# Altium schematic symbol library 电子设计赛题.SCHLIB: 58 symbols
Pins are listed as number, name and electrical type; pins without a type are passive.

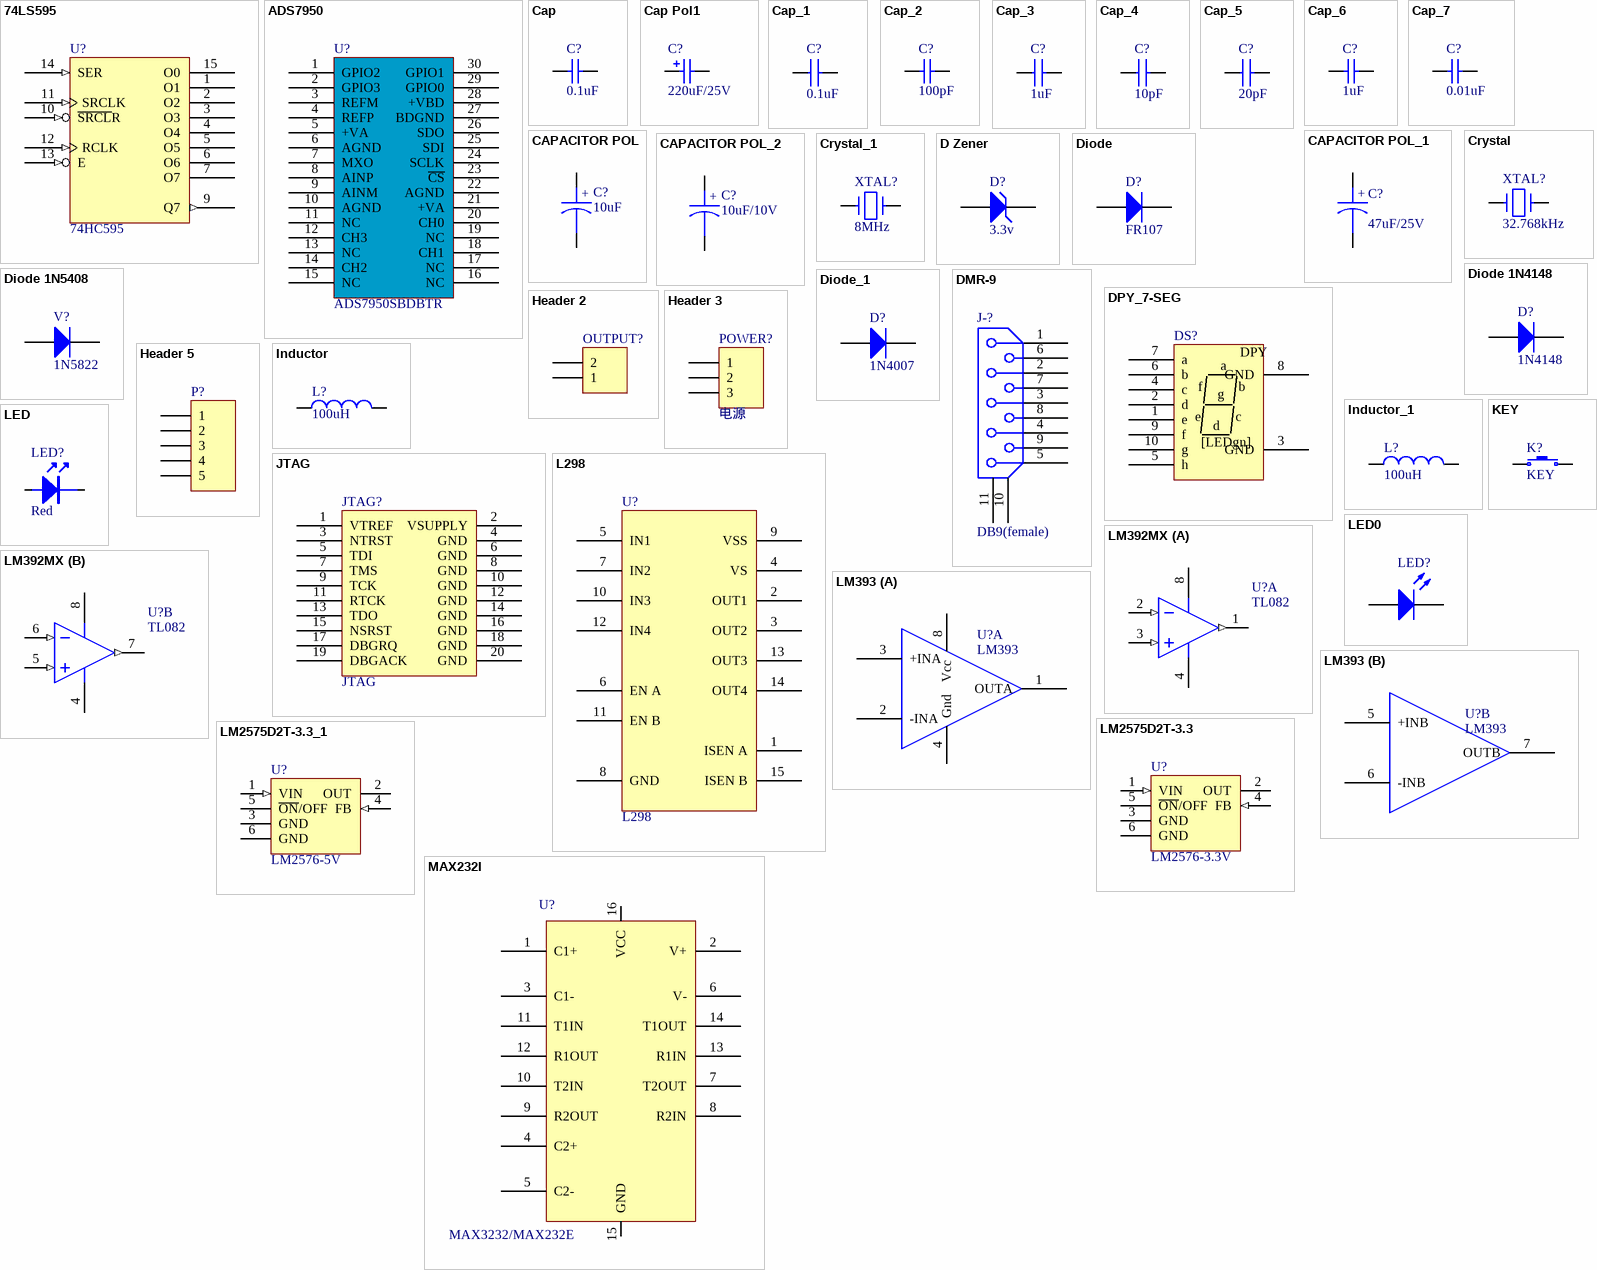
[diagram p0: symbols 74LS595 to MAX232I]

## 74LS595
designator U?, comment 74HC595
pins: 1 O1 (hiz), 2 O2 (hiz), 3 O3 (hiz), 4 O4 (hiz), 5 O5 (hiz), 6 O6 (hiz), 7 O7 (hiz), 8 GND (power) hidden to GND, 9 Q7 (out), 10 ~{SRCL}R (in), 11 SRCLK (in), 12 RCLK (in), 13 E (in), 14 SER (in), 15 O0 (hiz), 16 VCC (power) hidden to VCC

## ADS7950
designator U?, comment ADS7950SBDBTR
footprint LC-TSSOP-30
pins: 1 GPIO2, 2 GPIO3, 3 REFM, 4 REFP, 5 +VA, 6 AGND, 7 MXO, 8 AINP, 9 AINM, 10 AGND, 11 NC, 12 CH3, 13 NC, 14 CH2, 15 NC, 16 NC, 17 NC, 18 CH1, 19 NC, 20 CH0, 21 +VA, 22 AGND, 23 ~{CS}, 24 SCLK, 25 SDI, 26 SDO, 27 BDGND, 28 +VBD, 29 GPIO0, 30 GPIO1

## Cap
designator C?, comment 0.1uF
Capacitor
simulation model CAP (Capacitor)
signal-integrity model Cap
footprint LC-0805_C
pins: 1, 2

## Cap Pol1
designator C?, comment 220uF/25V
Polarized Capacitor (Radial)
simulation model CAP (Capacitor)
signal-integrity model Cap Pol
footprint CD-220uF-25V
pins: 1, 2
1 alternate drawing of the same symbol

## Cap_1
designator C?, comment 0.1uF
footprint LC-0805_C
pins: 1, 2

## Cap_2
designator C?, comment 100pF
Capacitor
simulation model CAP (Capacitor)
signal-integrity model Cap
footprint LC-0805_C
pins: 1, 2

## Cap_3
designator C?, comment 1uF
footprint LC-0805_C
pins: 1, 2

## Cap_4
designator C?, comment 10pF
footprint LC-0603_C
pins: 1, 2

## Cap_5
designator C?, comment 20pF
footprint LC-0603_C
pins: 1, 2

## Cap_6
designator C?, comment 1uF
Capacitor
simulation model CAP (Capacitor)
signal-integrity model Cap
footprint LC-0805_C
pins: 1, 2

## Cap_7
designator C?, comment 0.01uF
Capacitor
simulation model CAP (Capacitor)
signal-integrity model Cap
footprint LC-0603_C
pins: 1, 2

## CAPACITOR POL
designator C?, comment 10uF
Capacitor
footprint LC-0805_C
pins: 1, 2
2 alternate drawings of the same symbol

## CAPACITOR POL_1
designator C?, comment 47uF/25V
Capacitor
footprint LC-0603_C
pins: 1, 2
2 alternate drawings of the same symbol

## CAPACITOR POL_2
designator C?, comment 10uF/10V
Capacitor
footprint LC-0805_C
pins: 1, 2
2 alternate drawings of the same symbol

## Crystal
designator XTAL?, comment 32.768kHz
pins: 1, 2

## Crystal_1
designator XTAL?, comment 8MHz
pins: 1, 2

## D Zener
designator D?, comment 3.3v
Zener Diode
simulation model ZENER (Diode)
signal-integrity model D Zener
footprint LC-SOD-123
pins: 1 A, 2 K

## Diode
designator D?, comment FR107
Default Diode
simulation model DIODE (Diode)
signal-integrity model Diode
footprint 二极管  1N4007
pins: 1 A, 2 K

## Diode 1N4148
designator D?, comment 1N4148
High Conductance Fast Diode
footprint SMA
footprint LC-SMA(DO-214AC)_S4
pins: 1 A, 2 K

## Diode 1N5408
designator V?, comment 1N5822
3 Amp Medium Power Silicon Rectifier Diode
simulation model 1N5408 (DIODE)
signal-integrity model 1N5408
footprint SMA
footprint SMA
footprint LC-SMA(DO-214AC)_S4
pins: 1 A, 2 K

## Diode_1
designator D?, comment 1N4007
footprint LC-SMA(DO-214AC)_S1
pins: 1 A, 2 K

## DMR-9
designator J-?, comment DB9(female)
footprint DSUB1.385-2H9
pins: 1, 2, 3, 4, 5, 6, 7, 8, 9, 10, 11
2 alternate drawings of the same symbol

## DPY_7-SEG
designator DS?
Seven-Segment Display
footprint 数码管0.52 (LED, 7-Segment Display, 13 mm, RHD; 10 Leads; Row Space 15.24 mm; Pitch 2.54 mm)
pins: 1 e, 2 d, 3 GND, 4 c, 5 h, 6 b, 7 a, 8 GND, 9 f, 10 g

## Header 2
designator OUTPUT?, comment 2P端子  (value not drawn)
Header, 2-Pin
signal-integrity model Connector
footprint P485 (5mm间距485端子)
pins: 1, 2

## Header 3
designator POWER?, comment 电源
Header, 3-Pin
signal-integrity model Connector
footprint P485-3
pins: 1, 2, 3

## Header 5
designator P?  (value not drawn)
Header, 5-Pin
signal-integrity model Connector
footprint 2.54/5P
pins: 1, 2, 3, 4, 5

## Inductor
designator L?, comment 100uH
Inductor; Code_IEC: 1005
simulation model INDUCTOR (Inductor)
signal-integrity model Inductor
footprint CDRH125
pins: 1, 2

## Inductor_1
designator L?, comment 100uH
footprint LC-0805_R
pins: 1, 2

## JTAG
designator JTAG?
footprint IDC20 (2.54mm*20)
pins: 1 VTREF, 2 VSUPPLY, 3 NTRST, 4 GND, 5 TDI, 6 GND, 7 TMS, 8 GND, 9 TCK, 10 GND, 11 RTCK, 12 GND, 13 TDO, 14 GND, 15 NSRST, 16 GND, 17 DBGRQ, 18 GND, 19 DBGACK, 20 GND

## KEY
designator K?
footprint AN6X6
pins: 1, 2

## L298
designator U?
footprint L298
pins: 1 ISEN A, 2 OUT1, 3 OUT2, 4 VS, 5 IN1, 6 EN A, 7 IN2, 8 GND, 9 VSS, 10 IN3, 11 EN B, 12 IN4, 13 OUT3, 14 OUT4, 15 ISEN B

## LED
designator LED?, comment Red
footprint LC-0603_LED_S4
pins: 1, 2

## LED0
designator LED?, comment LED  (value not drawn)
Typical INFRARED GaAs LED
simulation model LED0 (Diode)
footprint LC-0805_LED_S1
pins: 1 A, 2 K

## LM392MX
designator U?, comment TL082
Low Power Operational Amplifier/Voltage Comparator; PartNumber: LM392MX; Manufacturer: National Semiconductor; PackageTopMarking: NSZXTT*LM392*M
footprint SOIC--8
footprint LC-SOIC-8_150mil
pins on every part: 4 GND (power), 8 V+ (power)
part A pins: 1 OUTA (out), 2 INA- (in), 3 INA+ (in)
part B pins: 5 INB+ (in), 6 INB- (in), 7 OUTB (out)

## LM393
designator U?
footprint SOIC--8
footprint LC-SOIC-8_150mil
part A pins: 1 OUTA, 2 -INA, 3 +INA, 4 Gnd, 8 Vcc
part B pins: 5 +INB, 6 -INB, 7 OUTB

## LM2575D2T-3.3
designator U?, comment LM2576-3.3V
Easy Switcher 1.0A Step-Down Voltage Regulator; Note: Pin 3 is electrically connected to Pin 6;Pin 6 is heatsink
footprint LC-TO-263-5
pins: 1 VIN (in), 2 OUT (oe), 3 GND (power), 4 FB (in), 5 ~{ON}/OFF, 6 GND (power)

## LM2575D2T-3.3_1
designator U?, comment LM2576-5V
Easy Switcher 1.0A Step-Down Voltage Regulator; Note: Pin 3 is electrically connected to Pin 6;Pin 6 is heatsink
footprint LC-TO-263-5
pins: 1 VIN (in), 2 OUT (oe), 3 GND (power), 4 FB (in), 5 ~{ON}/OFF, 6 GND (power)

## MAX232I
designator U?, comment MAX3232/MAX232E
Text Field1: 100; Text Field2: 200
footprint LC-SOIC-16_300mil
footprint LC-SOIC-16_300mil
footprint LC-SOP-16_300mil
pins: 1 C1+, 2 V+, 3 C1-, 4 C2+, 5 C2-, 6 V-, 7 T2OUT, 8 R2IN, 9 R2OUT, 10 T2IN, 11 T1IN, 12 R1OUT, 13 R1IN, 14 T1OUT, 15 GND, 16 VCC
2 alternate drawings of the same symbol

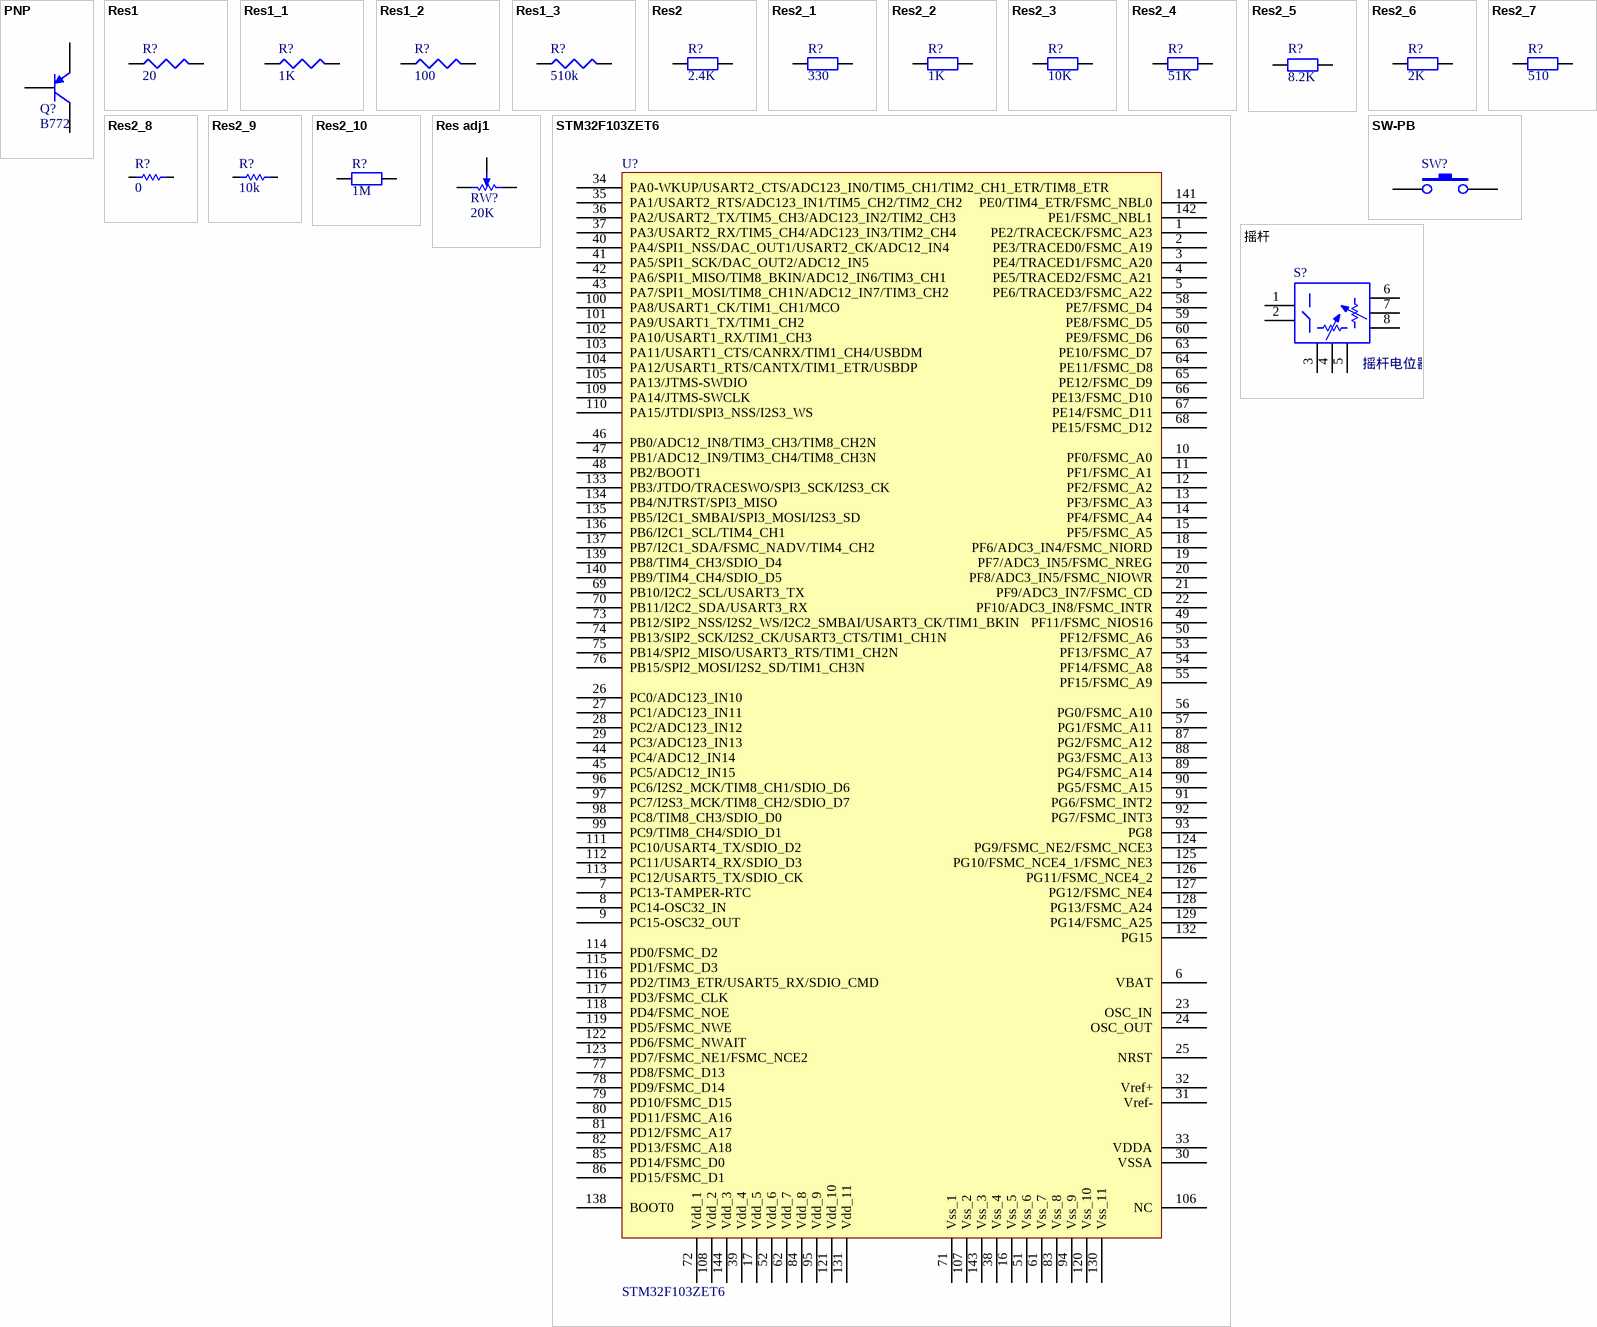
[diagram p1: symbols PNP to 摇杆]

## PNP
designator Q?, comment B772
PNP Bipolar Transistor
footprint SOT-23B_L (SOT23, 3-Leads, Body 2.9x1.3mm, Pitch 0.95mm, Lead Span 2.4mm, IPC High Density)
simulation model PNP
signal-integrity model PNP
pins: 1 B, 2 C, 3 E

## Res1
designator R?, comment 20
footprint LC-0805_R
pins: 1, 2

## Res1_1
designator R?, comment 1K
footprint LC-0805_R
pins: 1, 2

## Res1_2
designator R?, comment 100
footprint LC-0805_R
pins: 1, 2

## Res1_3
designator R?, comment 510k
footprint LC-0805_R
pins: 1, 2

## Res2
designator R?, comment 2.4K
Resistor
simulation model RESISTOR (Resistor)
signal-integrity model Res
footprint LC-0805_R
pins: 1, 2

## Res2_1
designator R?, comment 330
Resistor
simulation model RESISTOR (Resistor)
signal-integrity model Res
footprint LC-0805_R
pins: 1, 2

## Res2_2
designator R?, comment 1K
Resistor
simulation model RESISTOR (Resistor)
signal-integrity model Res
footprint LC-0805_R
pins: 1, 2

## Res2_3
designator R?, comment 10K
Resistor
simulation model RESISTOR (Resistor)
signal-integrity model Res
footprint LC-0805_R
pins: 1, 2

## Res2_4
designator R?, comment 51K
Resistor
simulation model RESISTOR (Resistor)
signal-integrity model Res
footprint LC-0805_R
pins: 1, 2

## Res2_5
designator R?, comment 8.2K
Resistor
simulation model RESISTOR (Resistor)
signal-integrity model Res
footprint LC-0805_R
pins: 1, 2

## Res2_6
designator R?, comment 2K
Resistor
simulation model RESISTOR (Resistor)
signal-integrity model Res
footprint LC-0805_R
pins: 1, 2

## Res2_7
designator R?, comment 510
Resistor
simulation model RESISTOR (Resistor)
signal-integrity model Res
footprint LC-0805_R
pins: 1, 2

## Res2_8
designator R?, comment 0
footprint LC-0805_R
pins: 1, 2

## Res2_9
designator R?, comment 10k
footprint LC-0805_R
pins: 1, 2

## Res2_10
designator R?, comment 1M
Resistor
simulation model RESISTOR (Resistor)
signal-integrity model Res
footprint LC-0603_R
pins: 1, 2

## Res adj1
designator RW?, comment 20K
footprint 3296W
pins: 1, 2, 3

## STM32F103ZET6
designator U?
footprint LC-TQFP-144_20x20x05P
footprint LC-LQFP-144_20x20x05P
pins: 1 PE2/TRACECK/FSMC_A23, 2 PE3/TRACED0/FSMC_A19, 3 PE4/TRACED1/FSMC_A20, 4 PE5/TRACED2/FSMC_A21, 5 PE6/TRACED3/FSMC_A22, 6 VBAT, 7 PC13-TAMPER-RTC, 8 PC14-OSC32_IN, 9 PC15-OSC32_OUT, 10 PF0/FSMC_A0, 11 PF1/FSMC_A1, 12 PF2/FSMC_A2, 13 PF3/FSMC_A3, 14 PF4/FSMC_A4, 15 PF5/FSMC_A5, 16 Vss_5, 17 Vdd_5, 18 PF6/ADC3_IN4/FSMC_NIORD, 19 PF7/ADC3_IN5/FSMC_NREG, 20 PF8/ADC3_IN5/FSMC_NIOWR, 21 PF9/ADC3_IN7/FSMC_CD, 22 PF10/ADC3_IN8/FSMC_INTR, 23 OSC_IN, 24 OSC_OUT, 25 NRST, 26 PC0/ADC123_IN10, 27 PC1/ADC123_IN11, 28 PC2/ADC123_IN12, 29 PC3/ADC123_IN13, 30 VSSA, 31 Vref-, 32 Vref+, 33 VDDA, 34 PA0-WKUP/USART2_CTS/ADC123_IN0/TIM5_CH1/TIM2_CH1_ETR/TIM8_ETR, 35 PA1/USART2_RTS/ADC123_IN1/TIM5_CH2/TIM2_CH2, 36 PA2/USART2_TX/TIM5_CH3/ADC123_IN2/TIM2_CH3, 37 PA3/USART2_RX/TIM5_CH4/ADC123_IN3/TIM2_CH4, 38 Vss_4, 39 Vdd_4, 40 PA4/SPI1_NSS/DAC_OUT1/USART2_CK/ADC12_IN4, 41 PA5/SPI1_SCK/DAC_OUT2/ADC12_IN5, 42 PA6/SPI1_MISO/TIM8_BKIN/ADC12_IN6/TIM3_CH1, 43 PA7/SPI1_MOSI/TIM8_CH1N/ADC12_IN7/TIM3_CH2, 44 PC4/ADC12_IN14, 45 PC5/ADC12_IN15, 46 PB0/ADC12_IN8/TIM3_CH3/TIM8_CH2N, 47 PB1/ADC12_IN9/TIM3_CH4/TIM8_CH3N, 48 PB2/BOOT1, 49 PF11/FSMC_NIOS16, 50 PF12/FSMC_A6, 51 Vss_6, 52 Vdd_6, 53 PF13/FSMC_A7, 54 PF14/FSMC_A8, 55 PF15/FSMC_A9, 56 PG0/FSMC_A10, 57 PG1/FSMC_A11, 58 PE7/FSMC_D4, 59 PE8/FSMC_D5, 60 PE9/FSMC_D6, 61 Vss_7, 62 Vdd_7, 63 PE10/FSMC_D7, 64 PE11/FSMC_D8, 65 PE12/FSMC_D9, 66 PE13/FSMC_D10, 67 PE14/FSMC_D11, 68 PE15/FSMC_D12, 69 PB10/I2C2_SCL/USART3_TX, 70 PB11/I2C2_SDA/USART3_RX, 71 Vss_1, 72 Vdd_1, 73 PB12/SIP2_NSS/I2S2_WS/I2C2_SMBAI/USART3_CK/TIM1_BKIN, 74 PB13/SIP2_SCK/I2S2_CK/USART3_CTS/TIM1_CH1N, 75 PB14/SPI2_MISO/USART3_RTS/TIM1_CH2N, 76 PB15/SPI2_MOSI/I2S2_SD/TIM1_CH3N, 77 PD8/FSMC_D13, 78 PD9/FSMC_D14, 79 PD10/FSMC_D15, 80 PD11/FSMC_A16, 81 PD12/FSMC_A17, 82 PD13/FSMC_A18, 83 Vss_8, 84 Vdd_8, 85 PD14/FSMC_D0, 86 PD15/FSMC_D1, 87 PG2/FSMC_A12, 88 PG3/FSMC_A13, 89 PG4/FSMC_A14, 90 PG5/FSMC_A15, 91 PG6/FSMC_INT2, 92 PG7/FSMC_INT3, 93 PG8, 94 Vss_9, 95 Vdd_9, 96 PC6/I2S2_MCK/TIM8_CH1/SDIO_D6, 97 PC7/I2S3_MCK/TIM8_CH2/SDIO_D7, 98 PC8/TIM8_CH3/SDIO_D0, 99 PC9/TIM8_CH4/SDIO_D1, 100 PA8/USART1_CK/TIM1_CH1/MCO, 101 PA9/USART1_TX/TIM1_CH2, 102 PA10/USART1_RX/TIM1_CH3, 103 PA11/USART1_CTS/CANRX/TIM1_CH4/USBDM, 104 PA12/USART1_RTS/CANTX/TIM1_ETR/USBDP, 105 PA13/JTMS-SWDIO, 106 NC, 107 Vss_2, 108 Vdd_2, 109 PA14/JTMS-SWCLK, 110 PA15/JTDI/SPI3_NSS/I2S3_WS, 111 PC10/USART4_TX/SDIO_D2, 112 PC11/USART4_RX/SDIO_D3, 113 PC12/USART5_TX/SDIO_CK, 114 PD0/FSMC_D2, 115 PD1/FSMC_D3, 116 PD2/TIM3_ETR/USART5_RX/SDIO_CMD, 117 PD3/FSMC_CLK, 118 PD4/FSMC_NOE, 119 PD5/FSMC_NWE, 120 Vss_10, 121 Vdd_10, 122 PD6/FSMC_NWAIT, 123 PD7/FSMC_NE1/FSMC_NCE2, 124 PG9/FSMC_NE2/FSMC_NCE3, 125 PG10/FSMC_NCE4_1/FSMC_NE3, 126 PG11/FSMC_NCE4_2, 127 PG12/FSMC_NE4, 128 PG13/FSMC_A24, 129 PG14/FSMC_A25, 130 Vss_11, 131 Vdd_11, 132 PG15, 133 PB3/JTDO/TRACESWO/SPI3_SCK/I2S3_CK, 134 PB4/NJTRST/SPI3_MISO, 135 PB5/I2C1_SMBAI/SPI3_MOSI/I2S3_SD, 136 PB6/I2C1_SCL/TIM4_CH1, 137 PB7/I2C1_SDA/FSMC_NADV/TIM4_CH2, 138 BOOT0, 139 PB8/TIM4_CH3/SDIO_D4, 140 PB9/TIM4_CH4/SDIO_D5, 141 PE0/TIM4_ETR/FSMC_NBL0, 142 PE1/FSMC_NBL1, 143 Vss_3, 144 Vdd_3

## SW-PB
designator SW?
footprint AN6X6
pins: 1, 2

## 摇杆
designator S?, comment 摇杆电位器
footprint 摇杆电位器
pins: 1, 2, 3, 4, 5, 6, 7, 8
